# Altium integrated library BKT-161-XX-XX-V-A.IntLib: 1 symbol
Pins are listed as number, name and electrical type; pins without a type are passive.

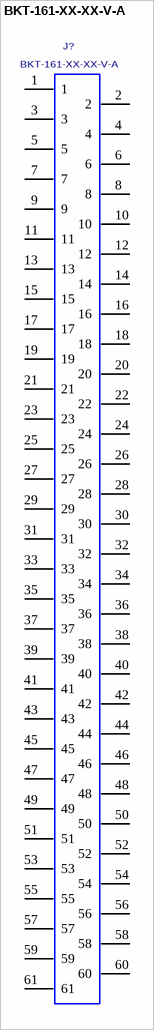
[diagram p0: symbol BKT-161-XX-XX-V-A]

## BKT-161-XX-XX-V-A
designator J?
1MM C.L. STAGGERED SURFACE MOUNT TERMINAL STRIP ASSEMBLY.; MANUFACTURER: SAMTEC
footprint BKT-161-XX-XX-V-A
pins: 1, 2, 3, 4, 5, 6, 7, 8, 9, 10, 11, 12, 13, 14, 15, 16, 17, 18, 19, 20, 21, 22, 23, 24, 25, 26, 27, 28, 29, 30, 31, 32, 33, 34, 35, 36, 37, 38, 39, 40, 41, 42, 43, 44, 45, 46, 47, 48, 49, 50, 51, 52, 53, 54, 55, 56, 57, 58, 59, 60, 61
